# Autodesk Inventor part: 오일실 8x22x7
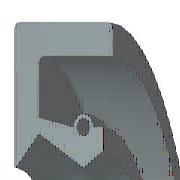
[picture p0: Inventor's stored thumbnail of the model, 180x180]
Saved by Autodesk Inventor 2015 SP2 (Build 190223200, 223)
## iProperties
IsCustomPart: 1
Created: 2009-02
Part Number: 오일실 8x22x7
Material: 고무
Description: 오일-실
Document SubType Name: Modeling
Standard: KS B 2804
Designer: 한국산업디자인학원
Standards Organization: KS
Language: ko-KR
Size Designation: D - 8 22 7
Categories: <MemberInstance><Categories><Category DisplayName="샤프트 부품" InternalName="7f7aeb1f-a693-4053-b835-cee3144e0d98" Mnemonic="SHFT"><Category DisplayName="실링" Intern
Density: 0.93 g/cm^3
Appearance: 고무 - 검은색 - 버전 1.1
Author: 한국산업디자인학원
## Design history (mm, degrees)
revolve "본체" stored, may be unused: angle "d17" = 90 deg
revolve "스프링1" stored, may be unused: angle "d18" = 90 deg
body "Solid1"
sketch "스케치1"
  geometry: L1 (0, 11)-(7, 11); L2 (7, 9.25)-(1.75, 9.25); L3 (1.75, 5.75)-(4.9, 4); L4 (4.9, 4)-(0, 4); L5 (0, 0)-(9.586, 0) reference; L6 (4.9, 4)-(6.3, 4.875); L7 (0, 18)-(0, -3) reference; L8 (-1.941, 0)-(11.507, 0) reference; L9 (4.2, 6.1)-(1.75, 6.59); L10 (1.75, 6.59)-(1.75, 9.25); L11 (0, 11)-(0, 4.088); L12 (4.9, 4)-(0, 4); L13 (1.75, 5.75)-(0.152, 4.028); L14 (7, 11)-(7, 9.25); L15 (5.6, 6.1)-(6.3, 6.1); L16 (6.3, 6.1)-(6.3, 4.875); C1 r 0.455 at (4.9, 6.1); A1 r 0.7 centre (4.9, 6.1) between (5.6, 6.1) and (4.2, 6.1); A2 r 0.088 centre (0.088, 4.088) between (0, 4.088) and (0.152, 4.028); 1 further point
  constraints: 28 end point, 5 horizontal alignment, 5 point on line, 4 point on circle, 4 vertical alignment, 3 centre point, 3 tangent, 2 collinear, 2 horizontal, 2 perpendicular, 1 coincident, 1 parallel
  dimensions: "d0" = 22 diameter of L1 L5 (= SD2); "d1" = 1.75 distance of L1.end L2.start (= SD); "d2" = 0.91 diameter of C1 (= SPDI); "d3" = 1.4 diameter of A1 (= SPDA); "d4" = 8 diameter of L3.end L5 (= NND); "d5" = 11.5 diameter of L3.start L5 (= TKDM); "d7" = 13.18 diameter of L9.end L5 (= TKDM + 0.24 x SWDT); "d8" = 1.75 distance between parallel lines of L11 L10 (= SD); "d9" = 4.9 distance from line of L11 C1.centre (= SPDST); "d10" = 12.2 diameter of C1.centre L5 (= HLDM); "d11" = 0.0875 radius of A2 (= 0.25 x LAB); "d12" = 6.3 distance between parallel lines of L11 L16 (= SDI); "d13" = 9.75 diameter of L6.end L5 (= ABDM); "d14" = 7 distance from line of L11 L1.end (= SWDT)
fillet "모깎기1" dims "d6" = 0.3 (= RR)
other parameters: "SD2" = 22 [user parameter; used in 1 equation term], "SWDT" = 7 [user parameter; used in 2 equation terms], "RR" = 0.3 [user parameter; used in 1 equation term], "SD" = 1.75 [user parameter; used in 2 equation terms], "NND" = 8 [user parameter; used in 1 equation term], "SPDA" = 1.4 [user parameter; used in 1 equation term], "SPDI" = 0.91 [user parameter; used in 1 equation term], "TKDM" = 11.5 [user parameter; used in 2 equation terms], "HLDM" = 12.2 [user parameter; used in 1 equation term], "ABDM" = 9.75 [user parameter; used in 1 equation term], "SDI" = 6.3 [user parameter; used in 1 equation term], "SPDST" = 4.9 [user parameter; used in 1 equation term], "LAB" = 0.35 [user parameter; used in 1 equation term], "d15" = 0, "d16" = 0, "d19" = 0
